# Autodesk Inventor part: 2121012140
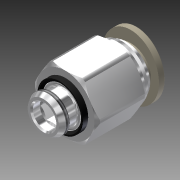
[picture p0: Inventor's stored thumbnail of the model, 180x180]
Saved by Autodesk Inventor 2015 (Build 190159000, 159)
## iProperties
Created: 2013-02
Part Number: 2121012140
Material: Generic
Document SubType Name: Modeling
Designer: Marci
Density: 1 g/cm^3
Appearance: Chrome - Polished
Translation Standard: STEP AP214IS
FileName: 2121012140
PreProcessor: PRO/ENGINEER BY PARAMETRIC TECHNOLOGY CORPORATION, 2006020
PostProcessor: Build: 160, Release: 2012 RTM - Date: Tue 03/01/2011
Sent Units: millimeter
Uncertainty: 0.004743499734357
Author: Marci
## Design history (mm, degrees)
node "21210121401"
thread "Thread1" dims "d0" = 10, "d1" = 0
node "2121012140"
node "Base1"
